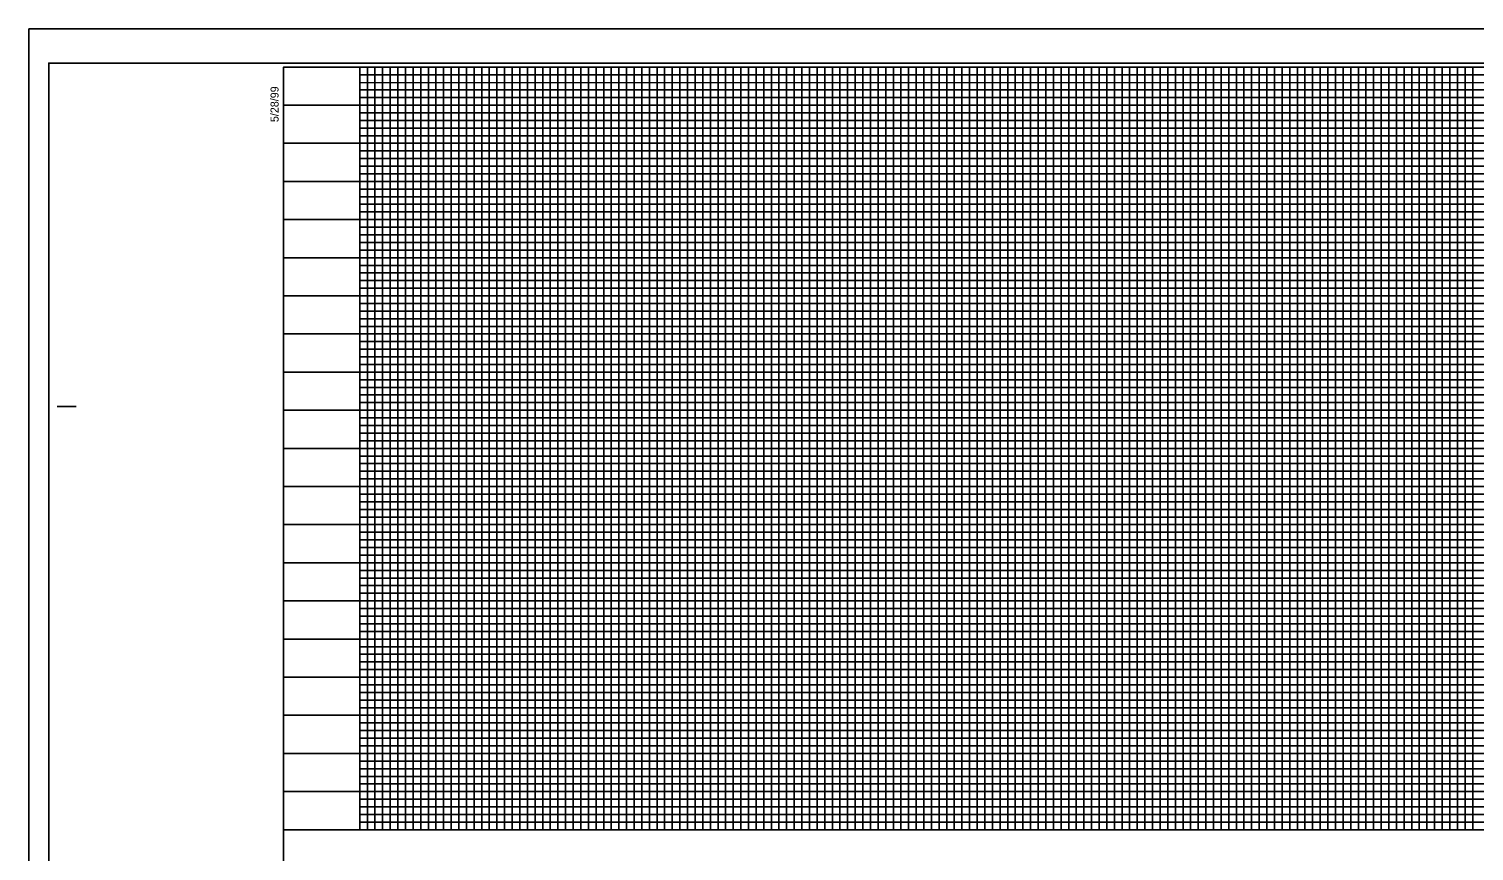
# Model space of a CAD drawing. Extents: x 2327371 to 2329279, y 159556 to 160656.
# Drawn here: x 2327371 to 2328319, y 160117 to 160656 of the extents above; entities that cross this region are included whole.
import ezdxf

# ---------------------------------------------------------------- set-up
doc = ezdxf.new("R2010")
doc.units = 0
for name, color, linetype in [('Scratch_Level_0', 7, 'Continuous'), ('Sheet Cutting Line CELL', 7, 'Continuous'), ('Sheet DOT Grid CELL', 7, 'Continuous'), ('Sheet Layout Profile Border Port 1', 7, 'Continuous'), ('Sheet Plot Border Inside CELL', 7, 'Continuous'), ('Sheet Plot Border Outside CELL', 7, 'Continuous'), ('Sheet Profile CELL', 7, 'Continuous'), ('Sheet Profile Grid Major CELL', 7, 'Continuous'), ('Sheet Profile Grid Middle CELL', 7, 'Continuous'), ('Sheet Profile Grid Minor CELL', 7, 'Continuous')]:
    doc.layers.add(name, color=color, linetype=linetype)

msp = doc.modelspace()

# ---------------------------------------------------------------- linework, layer by layer
at = {"layer": 'Scratch_Level_0'}
msp.add_lwpolyline([(2327587.98, 160131.31), (2327587.98, 160631.31), (2328837.98, 160631.31), (2328837.98, 160470.26), (2328987.98, 160470.26), (2328987.98, 160131.31)], close=True, dxfattribs=at)
at = {"layer": 'Sheet Cutting Line CELL'}
for p, q in [((2329054.98, 160656.31), (2327370.98, 160656.31)), ((2327370.98, 160656.31), (2327370.98, 159556.31))]:
    msp.add_line(p, q, dxfattribs=at)
at = {"layer": 'Sheet DOT Grid CELL'}
for p, q in [((2327587.98, 160131.31), (2327587.98, 160631.31)), ((2327637.98, 160131.31), (2327637.98, 160631.31)), ((2327687.98, 160131.31), (2327687.98, 160631.31)), ((2327737.98, 160131.31), (2327737.98, 160631.31)), ((2327787.98, 160131.31), (2327787.98, 160631.31)), ((2327837.98, 160131.31), (2327837.98, 160631.31)), ((2327887.98, 160131.31), (2327887.98, 160631.31)), ((2327937.98, 160131.31), (2327937.98, 160631.31)), ((2327987.98, 160131.31), (2327987.98, 160631.31)), ((2328037.98, 160131.31), (2328037.98, 160631.31)), ((2328087.98, 160131.31), (2328087.98, 160631.31)), ((2328137.98, 160131.31), (2328137.98, 160631.31)), ((2328187.98, 160131.31), (2328187.98, 160631.31)), ((2328237.98, 160131.31), (2328237.98, 160631.31)), ((2328287.98, 160131.31), (2328287.98, 160631.31)), ((2328837.93, 160581.31), (2327537.98, 160581.31)), ((2328837.93, 160531.31), (2327537.98, 160531.31)), ((2328837.98, 160481.31), (2327537.98, 160481.31)), ((2329037.98, 160431.31), (2327537.98, 160431.31)), ((2329037.98, 160381.31), (2327537.98, 160381.31)), ((2329037.98, 160331.31), (2327537.98, 160331.31)), ((2329037.98, 160281.31), (2327537.98, 160281.31)), ((2329037.98, 160231.31), (2327537.98, 160231.31)), ((2329037.98, 160181.31), (2327537.98, 160181.31))]:
    msp.add_line(p, q, dxfattribs=at)
at = {"layer": 'Sheet Layout Profile Border Port 1'}
msp.add_lwpolyline([(2327587.98, 160470.26), (2327587.98, 160131.31), (2328987.98, 160131.31), (2328987.98, 160470.26)], dxfattribs=at)
at = {"layer": 'Sheet Plot Border Inside CELL'}
msp.add_lwpolyline([(2327383.98, 159578.76), (2329050.48, 159578.76), (2329050.48, 160633.86), (2327383.98, 160633.86)], close=True, dxfattribs=at)
at = {"layer": 'Sheet Plot Border Outside CELL'}
msp.add_lwpolyline([(2327370.98, 159556.31), (2329054.98, 159556.31), (2329054.98, 160656.31), (2327370.98, 160656.31)], close=True, dxfattribs=at)
at = {"layer": 'Sheet Profile CELL'}
for p, q in [((2327389.48, 160408.81), (2327401.98, 160408.81)), ((2327537.98, 160131.31), (2329037.98, 160131.31))]:
    msp.add_line(p, q, dxfattribs=at)
msp.add_lwpolyline([(2329037.98, 160631.31), (2327537.98, 160631.31), (2327537.98, 159581.31), (2329037.98, 159581.31)], close=True, dxfattribs=at)
at = {"layer": 'Sheet Profile Grid Major CELL'}
for points in [[(2327587.98, 160631.31), (2327587.98, 160131.31), (2327637.98, 160131.31), (2327637.98, 160631.31), (2327687.98, 160631.31), (2327687.98, 160131.31), (2327737.98, 160131.31), (2327737.98, 160631.31), (2327787.98, 160631.31), (2327787.98, 160131.31), (2327837.98, 160131.31), (2327837.98, 160631.31), (2327887.98, 160631.31), (2327887.98, 160131.31), (2327937.98, 160131.31), (2327937.98, 160631.31), (2327987.98, 160631.31), (2327987.98, 160131.31), (2328037.98, 160131.31), (2328037.98, 160631.31), (2328087.98, 160631.31), (2328087.98, 160131.31), (2328137.98, 160131.31), (2328137.98, 160631.31), (2328187.98, 160631.31), (2328187.98, 160131.31), (2328237.98, 160131.31), (2328237.98, 160631.31), (2328287.98, 160631.31), (2328287.98, 160131.31), (2328337.98, 160131.31)], [(2327537.98, 160581.31), (2328837.98, 160581.31)], [(2328837.98, 160531.31), (2327537.98, 160531.31), (2327537.98, 160481.31), (2328837.98, 160481.31)], [(2329037.98, 160431.31), (2327537.98, 160431.31), (2327537.98, 160381.31), (2329037.98, 160381.31)], [(2329037.98, 160331.31), (2327537.98, 160331.31), (2327537.98, 160281.31), (2329037.98, 160281.31)], [(2329037.98, 160231.31), (2327537.98, 160231.31), (2327537.98, 160231.31), (2327537.98, 160181.31), (2329037.98, 160181.31)]]:
    msp.add_lwpolyline(points, dxfattribs=at)
at = {"layer": 'Sheet Profile Grid Middle CELL'}
msp.add_line((2327537.98, 160606.31), (2328837.93, 160606.31), dxfattribs=at)
for points in [[(2327612.98, 160631.31), (2327612.98, 160131.31), (2327662.98, 160131.31), (2327662.98, 160631.31), (2327712.98, 160631.31), (2327712.98, 160131.31), (2327762.98, 160131.31), (2327762.98, 160631.31), (2327812.98, 160631.31), (2327812.98, 160131.31), (2327862.98, 160131.31), (2327862.98, 160631.31), (2327912.98, 160631.31), (2327912.98, 160131.31), (2327962.98, 160131.31), (2327962.98, 160631.31), (2328012.98, 160631.31), (2328012.98, 160131.31), (2328062.98, 160131.31), (2328062.98, 160631.31), (2328112.98, 160631.31), (2328112.98, 160131.31), (2328162.98, 160131.31), (2328162.98, 160131.31), (2328162.98, 160631.31), (2328212.98, 160631.31), (2328212.98, 160131.31), (2328262.98, 160131.31), (2328262.98, 160631.31), (2328312.98, 160631.31), (2328312.98, 160131.31), (2328362.98, 160131.31)], [(2328837.98, 160556.31), (2327537.98, 160556.31), (2327537.98, 160506.31), (2328837.98, 160506.31)], [(2329037.98, 160456.31), (2327537.98, 160456.31), (2327537.98, 160406.31), (2328862.98, 160406.31)], [(2329037.98, 160356.31), (2327537.98, 160356.31), (2327537.98, 160306.31), (2329037.98, 160306.31)], [(2329037.98, 160256.31), (2327537.98, 160256.31), (2327537.98, 160206.31), (2329037.98, 160206.31)], [(2329037.98, 160156.31), (2327537.98, 160156.31)]]:
    msp.add_lwpolyline(points, dxfattribs=at)
at = {"layer": 'Sheet Profile Grid Minor CELL'}
for p, q in [((2327587.98, 160626.31), (2328837.98, 160626.31)), ((2327587.98, 160621.31), (2327587.98, 160621.31)), ((2328837.98, 160621.31), (2327587.98, 160620.96)), ((2327587.98, 160616.31), (2328837.98, 160616.31)), ((2328837.93, 160496.31), (2327587.98, 160496.31)), ((2328837.98, 160491.31), (2327587.98, 160491.31)), ((2328837.98, 160486.31), (2327587.98, 160486.31)), ((2327587.98, 160476.31), (2328837.98, 160476.31)), ((2328837.98, 160471.31), (2327587.98, 160471.31)), ((2327587.98, 160466.31), (2328987.98, 160466.31)), ((2328987.98, 160446.31), (2327587.98, 160446.31)), ((2327587.98, 160441.31), (2328987.98, 160441.31)), ((2328987.98, 160421.31), (2327587.98, 160421.31)), ((2327587.98, 160416.31), (2328987.98, 160416.31)), ((2328987.98, 160396.31), (2327587.98, 160396.31)), ((2327587.98, 160391.31), (2328987.98, 160391.31)), ((2328987.98, 160386.31), (2327587.98, 160386.31)), ((2327587.98, 160376.31), (2328987.98, 160376.31)), ((2328987.98, 160371.31), (2327587.98, 160371.31)), ((2327587.98, 160366.31), (2328987.98, 160366.31)), ((2328987.98, 160361.31), (2327587.98, 160361.31)), ((2327587.98, 160351.31), (2328987.98, 160351.31)), ((2328987.98, 160346.31), (2327587.98, 160346.31)), ((2327587.98, 160341.31), (2328987.98, 160341.31)), ((2328987.98, 160336.31), (2327587.98, 160336.31)), ((2327587.98, 160326.31), (2328987.98, 160326.31)), ((2328987.98, 160321.31), (2327587.98, 160321.31)), ((2327587.98, 160316.31), (2328987.98, 160316.31)), ((2328987.98, 160311.31), (2327587.98, 160311.31)), ((2327587.98, 160301.31), (2328987.98, 160301.31)), ((2328987.98, 160296.31), (2327587.98, 160296.31)), ((2327587.98, 160291.31), (2328987.98, 160291.31)), ((2328987.98, 160286.31), (2327587.98, 160286.31)), ((2327587.98, 160276.31), (2328987.98, 160276.31)), ((2328987.98, 160271.31), (2327587.98, 160271.31)), ((2327587.98, 160266.31), (2328987.98, 160266.31)), ((2328987.98, 160261.31), (2327587.98, 160261.31)), ((2327587.98, 160251.31), (2328987.98, 160251.31)), ((2328987.98, 160246.31), (2327587.98, 160246.31)), ((2328987.98, 160241.31), (2327587.98, 160241.31)), ((2328987.98, 160236.31), (2327587.98, 160236.31)), ((2327587.98, 160226.31), (2328987.98, 160226.31)), ((2328987.98, 160221.31), (2327587.98, 160221.31)), ((2327587.98, 160216.31), (2328987.98, 160216.31)), ((2328987.98, 160211.31), (2327587.98, 160211.31)), ((2327587.98, 160201.31), (2328987.98, 160201.31)), ((2328987.98, 160196.31), (2327587.98, 160196.31)), ((2327587.98, 160191.31), (2328987.98, 160191.31)), ((2328987.98, 160186.31), (2327587.98, 160186.31)), ((2327587.98, 160176.31), (2328987.98, 160176.31)), ((2328987.98, 160171.31), (2327587.98, 160171.31)), ((2327587.98, 160166.31), (2328987.98, 160166.31)), ((2328987.98, 160161.31), (2327587.98, 160161.31)), ((2327587.98, 160151.31), (2328987.98, 160151.31)), ((2328987.98, 160146.31), (2327587.98, 160146.31)), ((2327587.98, 160141.31), (2328987.98, 160141.31))]:
    msp.add_line(p, q, dxfattribs=at)
for points in [[(2327592.98, 160631.31), (2327592.98, 160131.31), (2327597.98, 160131.31), (2327597.98, 160631.31), (2327602.98, 160631.31), (2327602.98, 160131.31), (2327607.98, 160131.31), (2327607.98, 160631.31), (2327617.98, 160631.31), (2327617.98, 160131.31), (2327622.98, 160131.31), (2327622.98, 160631.31), (2327627.98, 160631.31), (2327627.98, 160131.31), (2327632.98, 160131.31), (2327642.98, 160131.31), (2327647.98, 160131.31), (2327647.98, 160631.31), (2327652.98, 160631.31), (2327652.98, 160131.31), (2327657.98, 160131.31), (2327657.98, 160631.31), (2327667.98, 160631.31), (2327667.98, 160131.31), (2327672.98, 160131.31), (2327672.98, 160631.31), (2327677.98, 160631.31), (2327677.98, 160131.31), (2327682.98, 160131.31), (2327682.98, 160631.31), (2327692.98, 160631.31), (2327692.98, 160131.31), (2327697.98, 160131.31), (2327697.98, 160631.31), (2327702.98, 160631.31), (2327702.98, 160131.31), (2327707.98, 160131.31), (2327707.98, 160631.31), (2327717.98, 160631.31), (2327717.98, 160131.31), (2327722.98, 160131.31), (2327722.98, 160631.31), (2327727.98, 160631.31), (2327727.98, 160131.31), (2327732.98, 160131.31), (2327732.98, 160631.31), (2327742.98, 160631.31), (2327742.98, 160131.31), (2327747.98, 160131.31), (2327747.98, 160631.31), (2327752.98, 160631.31), (2327752.98, 160131.31), (2327757.98, 160131.31), (2327757.98, 160631.31), (2327767.98, 160631.31), (2327767.98, 160131.31), (2327772.98, 160131.31), (2327772.98, 160631.31), (2327777.98, 160631.31), (2327777.98, 160131.31), (2327782.98, 160131.31), (2327782.98, 160631.31), (2327792.98, 160631.31), (2327792.98, 160131.31), (2327797.98, 160131.31), (2327797.98, 160631.31), (2327802.98, 160631.31), (2327802.98, 160131.31)], [(2327632.98, 160131.31), (2327632.98, 160631.31), (2327642.98, 160631.31), (2327642.98, 160131.31)], [(2327802.98, 160131.31), (2327807.98, 160131.31), (2327807.98, 160631.31), (2327817.98, 160631.31), (2327817.98, 160131.31), (2327822.98, 160131.31), (2327822.98, 160631.31), (2327827.98, 160631.31), (2327827.98, 160131.31), (2327832.98, 160131.31), (2327832.98, 160631.31), (2327842.98, 160631.31), (2327842.98, 160131.31), (2327847.98, 160131.31), (2327847.98, 160631.31), (2327852.98, 160631.31), (2327852.98, 160131.31), (2327857.98, 160131.31), (2327857.98, 160631.31), (2327867.98, 160631.31), (2327867.98, 160131.31), (2327872.98, 160131.31), (2327872.98, 160631.31), (2327877.98, 160631.31), (2327877.98, 160131.31), (2327882.98, 160131.31), (2327882.98, 160631.31), (2327892.98, 160631.31), (2327892.98, 160131.31), (2327897.98, 160131.31), (2327897.98, 160631.31), (2327902.98, 160631.31), (2327902.98, 160131.31), (2327907.98, 160131.31), (2327907.98, 160631.31), (2327917.98, 160631.31), (2327917.98, 160131.31), (2327922.98, 160131.31), (2327922.98, 160631.31), (2327927.98, 160631.31), (2327927.98, 160131.31), (2327932.98, 160131.31), (2327932.98, 160631.31), (2327942.98, 160631.31), (2327942.98, 160131.31), (2327947.98, 160131.31), (2327947.98, 160631.31), (2327952.98, 160631.31), (2327952.98, 160131.31), (2327957.98, 160131.31), (2327957.98, 160631.31), (2327967.98, 160631.31), (2327967.98, 160131.31), (2327972.98, 160131.31), (2327972.98, 160631.31), (2327977.98, 160631.31), (2327977.98, 160131.31), (2327982.98, 160131.31), (2327982.98, 160631.31), (2327992.98, 160631.31), (2327992.98, 160131.31), (2327997.98, 160131.31), (2327997.98, 160631.31), (2328002.98, 160631.31), (2328002.98, 160131.31), (2328007.98, 160131.31), (2328007.98, 160631.31), (2328017.98, 160631.31), (2328017.98, 160131.31), (2328022.98, 160131.31), (2328022.98, 160631.31), (2328027.98, 160631.31), (2328027.98, 160131.31), (2328032.98, 160131.31), (2328032.98, 160631.31), (2328042.98, 160631.31), (2328042.98, 160131.31), (2328047.98, 160131.31), (2328047.98, 160631.31), (2328052.98, 160631.31), (2328052.98, 160131.31), (2328057.98, 160131.31), (2328057.98, 160631.31), (2328067.98, 160631.31), (2328067.98, 160131.31), (2328072.98, 160131.31), (2328072.98, 160631.31), (2328077.98, 160631.31), (2328077.98, 160131.31), (2328082.98, 160131.31), (2328082.98, 160631.31), (2328092.98, 160631.31), (2328092.98, 160131.31), (2328097.98, 160131.31), (2328097.98, 160631.31), (2328102.98, 160631.31), (2328102.98, 160131.31), (2328107.98, 160131.31), (2328107.98, 160631.31), (2328117.98, 160631.31)], [(2328117.98, 160631.31), (2328117.98, 160131.31), (2328122.98, 160131.31), (2328122.98, 160631.31), (2328127.98, 160631.31), (2328127.98, 160131.31), (2328132.98, 160131.31), (2328132.98, 160631.31), (2328142.98, 160631.31), (2328142.98, 160131.31), (2328147.98, 160131.31), (2328147.98, 160631.31), (2328152.98, 160631.31), (2328152.98, 160131.31), (2328157.98, 160131.31), (2328157.98, 160631.31), (2328167.98, 160631.31), (2328167.98, 160131.31), (2328172.98, 160131.31), (2328172.98, 160631.31), (2328177.98, 160631.31), (2328177.98, 160131.31), (2328182.98, 160131.31), (2328182.98, 160631.31), (2328192.98, 160631.31), (2328192.98, 160131.31), (2328197.98, 160131.31), (2328197.98, 160631.31), (2328202.98, 160631.31), (2328202.98, 160131.31), (2328207.98, 160131.31), (2328207.98, 160631.31), (2328217.98, 160631.31), (2328217.98, 160131.31), (2328222.98, 160131.31), (2328222.98, 160631.31), (2328227.98, 160631.31), (2328227.98, 160131.31), (2328232.98, 160131.31), (2328232.98, 160631.31), (2328242.98, 160631.31), (2328242.98, 160131.31), (2328242.98, 160131.31), (2328247.98, 160131.31), (2328247.98, 160631.31), (2328252.98, 160631.31), (2328252.98, 160131.31), (2328257.98, 160131.31), (2328257.98, 160631.31), (2328267.98, 160631.31), (2328267.98, 160131.31), (2328272.98, 160131.31), (2328272.98, 160631.31), (2328277.98, 160631.31), (2328277.98, 160131.31), (2328282.98, 160131.31), (2328282.98, 160631.31), (2328292.98, 160631.31), (2328292.98, 160131.31), (2328297.98, 160131.31), (2328297.98, 160631.31), (2328302.98, 160631.31), (2328302.98, 160131.31), (2328307.98, 160131.31), (2328307.98, 160631.31), (2328317.98, 160631.31), (2328317.98, 160131.31), (2328322.98, 160131.31)], [(2328837.98, 160611.31), (2327587.98, 160611.31), (2327587.98, 160601.31), (2328837.98, 160601.31)], [(2328837.93, 160596.31), (2327587.98, 160596.31), (2327587.98, 160591.31), (2328837.98, 160591.31)], [(2328837.98, 160586.31), (2327587.98, 160586.31), (2327587.98, 160576.31), (2328837.98, 160576.31)], [(2328837.98, 160571.31), (2327587.98, 160571.31), (2327587.98, 160566.31), (2328837.98, 160566.31)], [(2328837.98, 160561.31), (2327587.98, 160561.31), (2327587.98, 160551.31), (2328837.98, 160551.31)], [(2328837.98, 160546.31), (2327587.98, 160546.31), (2327587.98, 160541.31), (2328837.98, 160541.31)], [(2328837.98, 160536.31), (2327587.98, 160536.31), (2327587.98, 160526.31), (2328837.98, 160526.31)], [(2328837.98, 160521.21), (2327588.08, 160521.21), (2327588.08, 160516.31), (2328837.98, 160516.31)], [(2328837.98, 160511.31), (2327587.98, 160511.31), (2327587.98, 160501.31), (2328837.98, 160501.31)], [(2328987.98, 160461.31), (2327587.98, 160461.31), (2327587.98, 160451.31), (2328987.98, 160451.31)], [(2328987.98, 160436.31), (2327587.98, 160436.31), (2327587.98, 160426.31), (2328987.98, 160426.31)], [(2328987.98, 160411.31), (2327587.98, 160411.31), (2327587.98, 160401.31), (2328987.98, 160401.31)], [(2328987.98, 160136.31), (2327587.98, 160136.31)]]:
    msp.add_lwpolyline(points, dxfattribs=at)

# ---------------------------------------------------------------- texts
at = {"layer": 'Sheet Profile CELL'}
msp.add_text('5/28/99', height=5.25, rotation=90, dxfattribs=at).set_placement((2327534.74, 160595.22))

doc.saveas('drawing.dxf')
